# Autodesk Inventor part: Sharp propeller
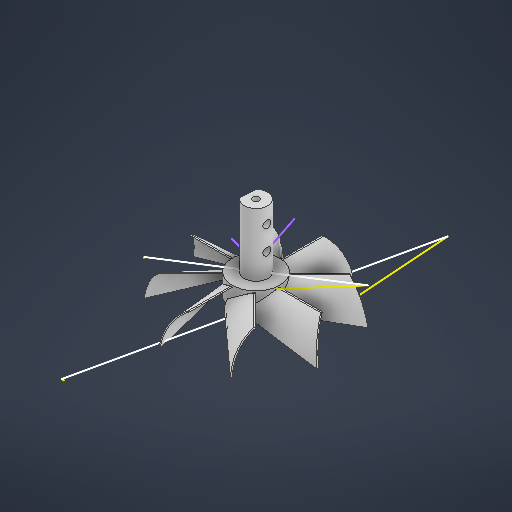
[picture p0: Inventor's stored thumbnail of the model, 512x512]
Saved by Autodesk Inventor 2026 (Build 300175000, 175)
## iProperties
Created: 2025-10
Part Number: Sharp propeller
Material: Generic
Document SubType Name: Modeling
Designer: sab273
Density: 1 g/cm^3
Appearance: Default
Author: sab273
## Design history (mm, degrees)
sketch "Sketch14"
  geometry: L1 (0, 0)-(0, 0); L2 (0, 0)-(-2, 0); L3 (-2, 0)-(-2, -84.166); L4 (-2, -84.166)-(0, -84.166); L5 (0, -84.166)-(0, 0); C1 r 30 at (0, 0)
  constraints: 10 end point, 2 parallel, 1 centre point, 1 coincident, 1 horizontal, 1 perpendicular, 1 vertical
  dimensions: "d52" = 2 distance of L4.end L3.end; "d63" = 60 diameter of C1
sketch "Sketch15"
  geometry: L1 (0, 0)-(-15.415, 5.723); L2 (0, 0)-(-10.016, 11.069)
  constraints: 4 end point
sketch "Sketch16"
  geometry: L1 (0, 0)-(12.16, -24.409)
  constraints: 2 end point
sketch "Sketch17"
  geometry: L1 (0, 0)-(15.43, -36.942); L2 (0, 0)-(-15.128, 22.419); L3 (0, 0)-(16.338, 21.572)
  constraints: 6 end point
coil "Coil1" sketch "Sketch17" pitch "d54" = 70; turns "d56" = 0.1; dims "d55" = 10, "d57" = 80 deg, angle "d58" = 90 deg, angle "d59" = 90 deg, "d60" = 0, "d61" = 0
sketch "Sketch18"
  geometry: L1 (0, 0)-(2, 0) reference; C1 r 30 at (0, 0); 1 further point
  constraints: 1 centre point
  dimensions: "d62" = 60 diameter of C1
extrude "Extrusion9" join sketch "Sketch18" distance "d64" = 2; taper "d66" = 0 deg; dims "d65" = 25, "d67" = 0
pattern_circular "Circular Pattern2" dims angle "d69" = 360 deg
sketch "Sketch19"
  geometry: L1 (-21.221, 100.616)-(-22.896, 100.48) reference; L2 (26.938, -18.838)-(21.221, -100.616) reference; L3 (-22.896, 100.48)-(21.221, -100.616); 1 further point
  constraints: 2 end point
node "Direct Edit1"
sketch "Sketch20"
  geometry: L1 (16.184, -2.864)-(43.076, 28.07) reference; L2 (-43.076, -28.07)-(-43.62, -27.43) reference; L3 (43.076, 28.07)-(-43.62, -27.43); 1 further point
  constraints: 2 end point
sketch "Sketch21"
  geometry: C1 r 7.5 at (0, 0); 1 further point
  constraints: 1 centre point, 1 coincident
  dimensions: "d74" = 15 diameter of C1
extrude "Extrusion10" join sketch "Sketch21" taper "d76" = 0 deg; distance "d77" = 40
sketch "Sketch22"
  geometry: C1 r 2.05 at (0, 0); 1 further point
  constraints: 1 centre point, 1 coincident
  dimensions: "d78" = 4.1 diameter of C1
extrude "Extrusion11" cut sketch "Sketch22" taper "d80" = 0 deg; distance "d81" = 60
sketch "Sketch23"
  geometry: L1 (-5.774, -4.786)-(-5.377, 5.228); A1 r 7.5 centre (0, 0) between (-5.774, -4.786) and (-5.377, 5.228) reference; A2 r 7.5 centre (0, 0) between (-5.774, -4.786) and (-7.494, 0.297)
  constraints: 6 point on circle, 2 end point, 1 centre point, 1 concentric
extrude "Extrusion12" cut sketch "Sketch23" taper "d83" = 0 deg; distance "d84" = 40
sketch "Sketch24"
  geometry: L1 (40, -12.511)-(40, 2.489) reference; C1 r 2.4 at (30, -5.011); C2 r 2.4 at (15, -5.011); 3 further points
  constraints: 2 centre point
extrude "Extrusion13" cut sketch "Sketch24" taper "d86" = 0 deg; distance "d87" = 40
body "Solid2"
feature "Scale1"
other parameters: "d71" = 5
